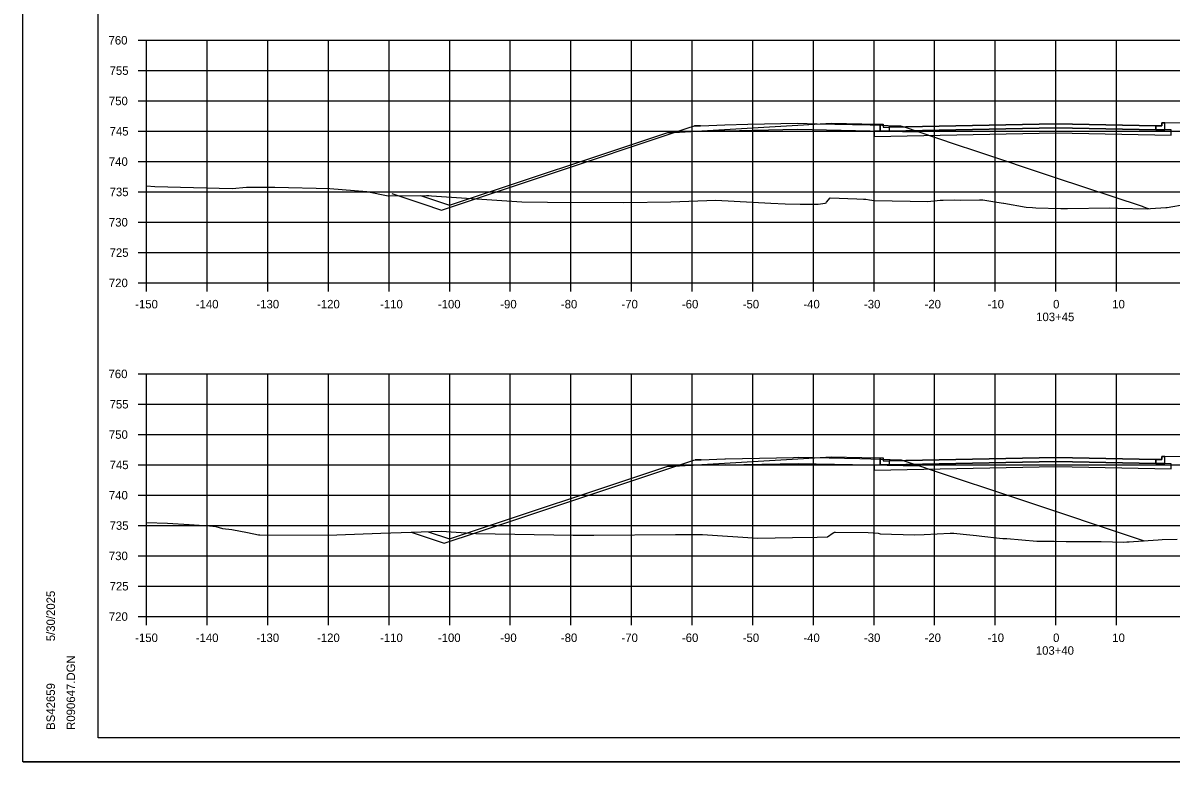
# Model space of a CAD drawing. Extents: x 1202951 to 1376887, y 378065 to 728038.
# Drawn here: x 1374114.6 to 1374304, y 379186.6 to 379308.5 of the extents above; entities that cross this region are included whole.
import ezdxf

# ---------------------------------------------------------------- set-up
doc = ezdxf.new("R2010")
doc.units = 0
for name, color, linetype in [('Default', 7, 'Continuous'), ('R_Alt Surface', 7, 'Continuous'), ('R_Axis', 7, 'Continuous'), ('R_Axis Annot', 7, 'Continuous'), ('R_Exist Surface', 7, 'Continuous'), ('R_Fin Surface', 7, 'Continuous'), ('R_Grid', 7, 'Continuous'), ('R_No Plot', 7, 'Continuous'), ('R_Proposed Road', 7, 'Continuous')]:
    doc.layers.add(name, color=color, linetype=linetype)

msp = doc.modelspace()

# ---------------------------------------------------------------- linework, layer by layer
at = {"layer": 'Default'}
for points in [[(1374255.98, 379291.78), (1374256.47, 379291.78), (1374256.48, 379291.28), (1374257.48, 379291.3), (1374257.48, 379290.64), (1374255.98, 379290.61)], [(1374302.98, 379292), (1374302.49, 379292), (1374302.48, 379291.5), (1374301.48, 379291.52), (1374301.48, 379290.86), (1374302.98, 379290.83)], [(1374255.98, 379236.77), (1374256.47, 379236.77), (1374256.48, 379236.27), (1374257.48, 379236.29), (1374257.48, 379235.62), (1374255.98, 379235.59)], [(1374302.98, 379236.99), (1374302.49, 379236.99), (1374302.48, 379236.49), (1374301.48, 379236.51), (1374301.48, 379235.84), (1374302.98, 379235.81)]]:
    msp.add_lwpolyline(points, close=True, dxfattribs=at)
at = {"layer": 'R_Alt Surface'}
for points in [[(1374284.98, 379291.19), (1374257.48, 379290.64), (1374255.98, 379290.61), (1374254.98, 379290.59), (1374254.98, 379289.75), (1374284.98, 379290.35), (1374303.98, 379289.97), (1374303.98, 379290.81), (1374302.98, 379290.83), (1374301.48, 379290.86)], [(1374257.48, 379291.3), (1374257.48, 379290.64), (1374284.98, 379291.19), (1374301.48, 379290.86), (1374301.48, 379291.52), (1374301.48, 379291.52), (1374284.98, 379291.85), (1374257.48, 379291.3)], [(1374257.48, 379236.29), (1374257.48, 379235.62), (1374284.98, 379236.17), (1374301.48, 379235.84), (1374301.48, 379236.51), (1374301.48, 379236.51), (1374284.98, 379236.84), (1374257.48, 379236.29)], [(1374284.98, 379236.17), (1374257.48, 379235.62), (1374255.98, 379235.59), (1374254.98, 379235.57), (1374254.98, 379234.74), (1374284.98, 379235.34), (1374303.98, 379234.96), (1374303.98, 379235.79), (1374302.98, 379235.81), (1374301.48, 379235.84)]]:
    msp.add_lwpolyline(points, close=True, dxfattribs=at)
for points in [[(1374255.98, 379291.78), (1374255.98, 379290.61), (1374257.48, 379290.64), (1374284.98, 379291.19), (1374301.48, 379290.86), (1374302.98, 379290.83), (1374302.98, 379292)], [(1374230.36, 379290.68), (1374222.36, 379290.52)], [(1374230.36, 379290.68), (1374242.36, 379290.92), (1374254.36, 379290.67)], [(1374254.36, 379290.67), (1374262.36, 379290.51)], [(1374255.98, 379236.77), (1374255.98, 379235.59), (1374257.48, 379235.62), (1374284.98, 379236.17), (1374301.48, 379235.84), (1374302.98, 379235.81), (1374302.98, 379236.99)], [(1374230.46, 379235.61), (1374222.46, 379235.45)], [(1374230.46, 379235.61), (1374242.46, 379235.85), (1374254.47, 379235.6)], [(1374254.47, 379235.6), (1374262.48, 379235.44)]]:
    msp.add_lwpolyline(points, dxfattribs=at)
at = {"layer": 'R_Axis'}
for p, q in [((1374133.58, 379305.6), (1374134.98, 379305.6)), ((1374134.98, 379265.6), (1374134.98, 379305.6)), ((1374133.58, 379300.6), (1374134.98, 379300.6)), ((1374133.58, 379295.6), (1374134.98, 379295.6)), ((1374133.58, 379290.6), (1374134.98, 379290.6)), ((1374133.58, 379285.6), (1374134.98, 379285.6)), ((1374133.58, 379280.6), (1374134.98, 379280.6)), ((1374133.58, 379275.6), (1374134.98, 379275.6)), ((1374133.58, 379270.6), (1374134.98, 379270.6)), ((1374133.58, 379265.6), (1374134.98, 379265.6)), ((1374134.98, 379265.6), (1374434.98, 379265.6)), ((1374134.98, 379264.2), (1374134.98, 379265.6)), ((1374144.98, 379264.2), (1374144.98, 379265.6)), ((1374154.98, 379264.2), (1374154.98, 379265.6)), ((1374164.98, 379264.2), (1374164.98, 379265.6)), ((1374174.98, 379264.2), (1374174.98, 379265.6)), ((1374184.98, 379264.2), (1374184.98, 379265.6)), ((1374194.98, 379264.2), (1374194.98, 379265.6)), ((1374204.98, 379264.2), (1374204.98, 379265.6)), ((1374214.98, 379264.2), (1374214.98, 379265.6)), ((1374224.98, 379264.2), (1374224.98, 379265.6)), ((1374234.98, 379264.2), (1374234.98, 379265.6)), ((1374244.98, 379264.2), (1374244.98, 379265.6)), ((1374254.98, 379264.2), (1374254.98, 379265.6)), ((1374264.98, 379264.2), (1374264.98, 379265.6)), ((1374274.98, 379264.2), (1374274.98, 379265.6)), ((1374284.98, 379264.2), (1374284.98, 379265.6)), ((1374294.98, 379264.2), (1374294.98, 379265.6)), ((1374133.58, 379250.6), (1374134.98, 379250.6)), ((1374134.98, 379210.6), (1374134.98, 379250.6)), ((1374133.58, 379245.6), (1374134.98, 379245.6)), ((1374133.58, 379240.6), (1374134.98, 379240.6)), ((1374133.58, 379235.6), (1374134.98, 379235.6)), ((1374133.58, 379230.6), (1374134.98, 379230.6)), ((1374133.58, 379225.6), (1374134.98, 379225.6)), ((1374133.58, 379220.6), (1374134.98, 379220.6)), ((1374133.58, 379215.6), (1374134.98, 379215.6)), ((1374133.58, 379210.6), (1374134.98, 379210.6)), ((1374134.98, 379210.6), (1374434.98, 379210.6)), ((1374134.98, 379209.2), (1374134.98, 379210.6)), ((1374144.98, 379209.2), (1374144.98, 379210.6)), ((1374154.98, 379209.2), (1374154.98, 379210.6)), ((1374164.98, 379209.2), (1374164.98, 379210.6)), ((1374174.98, 379209.2), (1374174.98, 379210.6)), ((1374184.98, 379209.2), (1374184.98, 379210.6)), ((1374194.98, 379209.2), (1374194.98, 379210.6)), ((1374204.98, 379209.2), (1374204.98, 379210.6)), ((1374214.98, 379209.2), (1374214.98, 379210.6)), ((1374224.98, 379209.2), (1374224.98, 379210.6)), ((1374234.98, 379209.2), (1374234.98, 379210.6)), ((1374244.98, 379209.2), (1374244.98, 379210.6)), ((1374254.98, 379209.2), (1374254.98, 379210.6)), ((1374264.98, 379209.2), (1374264.98, 379210.6)), ((1374274.98, 379209.2), (1374274.98, 379210.6)), ((1374284.98, 379209.2), (1374284.98, 379210.6)), ((1374294.98, 379209.2), (1374294.98, 379210.6))]:
    msp.add_line(p, q, dxfattribs=at)
at = {"layer": 'R_Exist Surface'}
for points in [[(1374134.98, 379281.61), (1374136.31, 379281.52), (1374149.08, 379281.15), (1374151.45, 379281.36), (1374156.13, 379281.36), (1374165.19, 379281.14), (1374171.28, 379280.67), (1374174.8, 379279.96), (1374181.16, 379280.02), (1374181.55, 379280), (1374181.99, 379279.95), (1374196.86, 379278.96), (1374201.1, 379278.89), (1374213.7, 379278.88), (1374221.44, 379278.96), (1374228.91, 379279.23), (1374237.97, 379278.76), (1374240.32, 379278.62), (1374242.8, 379278.57), (1374245.77, 379278.59), (1374246.9, 379278.77), (1374247.07, 379278.79), (1374247.14, 379278.9), (1374247.76, 379279.6), (1374252.12, 379279.46), (1374253.26, 379279.4), (1374253.63, 379279.4), (1374254.21, 379279.28), (1374254.63, 379279.22), (1374255.07, 379279.21), (1374263.84, 379279), (1374265.9, 379279.24), (1374266.41, 379279.25), (1374268.25, 379279.28), (1374269.28, 379279.25), (1374272.38, 379279.27), (1374272.92, 379279.27), (1374275.26, 379278.91), (1374276.34, 379278.74), (1374276.4, 379278.73), (1374280.1, 379278.09), (1374281.14, 379278.01), (1374281.66, 379278), (1374285.79, 379277.85), (1374286.9, 379277.85), (1374293.9, 379277.97), (1374295.2, 379277.94), (1374300.09, 379277.83), (1374300.62, 379277.87), (1374303.14, 379278.06), (1374303.34, 379278.06), (1374309.63, 379279.12)], [(1374134.98, 379226.12), (1374138.41, 379226.02), (1374142.01, 379225.76), (1374145.37, 379225.57), (1374146.39, 379225.45), (1374147.49, 379225.14), (1374149.05, 379224.97), (1374151.6, 379224.46), (1374153.42, 379224.07), (1374153.64, 379224.08), (1374154.84, 379224.03), (1374166.37, 379224.08), (1374173.63, 379224.34), (1374183.65, 379224.66), (1374189.3, 379224.28), (1374205.34, 379224), (1374208.74, 379224), (1374222.22, 379224.14), (1374226.71, 379224.1), (1374235.81, 379223.52), (1374241.54, 379223.63), (1374245.59, 379223.67), (1374247.29, 379223.73), (1374248.24, 379224.41), (1374248.38, 379224.47), (1374248.4, 379224.49), (1374248.61, 379224.49), (1374254.02, 379224.47), (1374255.69, 379224.36), (1374255.99, 379224.22), (1374261.66, 379224.05), (1374263.24, 379224.11), (1374267.56, 379224.35), (1374268.13, 379224.36), (1374269.68, 379224.19), (1374271.87, 379223.98), (1374272.79, 379223.86), (1374275.67, 379223.53), (1374276.22, 379223.45), (1374276.63, 379223.46), (1374276.89, 379223.44), (1374281.86, 379223.04), (1374284.68, 379223.02), (1374286.66, 379222.95), (1374290.13, 379222.95), (1374292.43, 379222.99), (1374296.2, 379222.88), (1374296.67, 379222.91), (1374297.1, 379222.89), (1374297.77, 379222.95), (1374301.86, 379223.24), (1374302.52, 379223.29), (1374304.99, 379223.34)]]:
    msp.add_lwpolyline(points, dxfattribs=at)
at = {"layer": 'R_Fin Surface'}
for points in [[(1374175.43, 379280.35), (1374180.56, 379278.65), (1374183.64, 379277.62), (1374201.61, 379283.61), (1374222.36, 379290.52), (1374224.31, 379291.17), (1374225.36, 379291.52), (1374225.7, 379291.52), (1374226.36, 379291.52), (1374227.72, 379291.57), (1374230.36, 379291.68), (1374234.19, 379291.75), (1374242.36, 379291.92), (1374245.59, 379291.85), (1374254.36, 379291.67), (1374255.24, 379291.64), (1374258.36, 379291.51), (1374259.16, 379291.51), (1374259.36, 379291.51), (1374259.95, 379291.32), (1374262.36, 379290.51), (1374268.56, 379288.44), (1374271.56, 379287.44), (1374284.89, 379283), (1374299.22, 379278.23), (1374299.45, 379278.15), (1374300.2, 379277.89), (1374300.32, 379277.85)], [(1374180.14, 379280.01), (1374184.97, 379278.4), (1374220.97, 379290.4), (1374221.97, 379290.4), (1374247.98, 379291.94), (1374252.98, 379291.84), (1374255.98, 379291.78), (1374256.47, 379291.78), (1374256.48, 379291.28), (1374257.48, 379291.3), (1374284.98, 379291.85), (1374301.48, 379291.52), (1374302.48, 379291.5), (1374302.49, 379292), (1374302.98, 379292), (1374305.98, 379292.06), (1374310.98, 379292.16), (1374312.32, 379291.72), (1374355.87, 379277.2), (1374357.22, 379277.65)], [(1374178.6, 379224.5), (1374180.77, 379223.78), (1374184.08, 379222.68), (1374195.07, 379226.34), (1374222.46, 379235.45), (1374225.28, 379236.39), (1374225.46, 379236.45), (1374226.41, 379236.45), (1374226.46, 379236.45), (1374230.37, 379236.61), (1374230.46, 379236.61), (1374233.26, 379236.67), (1374241.69, 379236.83), (1374242.46, 379236.85), (1374252.62, 379236.64), (1374254.47, 379236.6), (1374257.67, 379236.47), (1374258.47, 379236.44), (1374258.69, 379236.44), (1374259.47, 379236.44), (1374261.76, 379235.68), (1374262.48, 379235.44), (1374264.56, 379234.75), (1374278.82, 379229.98), (1374299.36, 379223.13), (1374299.54, 379223.07)], [(1374181.4, 379224.59), (1374184.96, 379223.4), (1374220.96, 379235.4), (1374221.96, 379235.4), (1374247.98, 379236.93), (1374252.98, 379236.83), (1374255.98, 379236.77), (1374256.47, 379236.77), (1374256.48, 379236.27), (1374257.48, 379236.29), (1374284.98, 379236.84), (1374301.48, 379236.51), (1374302.48, 379236.49), (1374302.49, 379236.99), (1374302.98, 379236.99), (1374305.98, 379237.05)]]:
    msp.add_lwpolyline(points, dxfattribs=at)
at = {"layer": 'R_Grid'}
for p, q in [((1374134.98, 379305.6), (1374434.98, 379305.6)), ((1374134.98, 379265.6), (1374134.98, 379305.6)), ((1374144.98, 379265.6), (1374144.98, 379305.6)), ((1374154.98, 379265.6), (1374154.98, 379305.6)), ((1374164.98, 379265.6), (1374164.98, 379305.6)), ((1374174.98, 379265.6), (1374174.98, 379305.6)), ((1374184.98, 379265.6), (1374184.98, 379305.6)), ((1374194.98, 379265.6), (1374194.98, 379305.6)), ((1374204.98, 379265.6), (1374204.98, 379305.6)), ((1374214.98, 379265.6), (1374214.98, 379305.6)), ((1374224.98, 379265.6), (1374224.98, 379305.6)), ((1374234.98, 379265.6), (1374234.98, 379305.6)), ((1374244.98, 379265.6), (1374244.98, 379305.6)), ((1374254.98, 379265.6), (1374254.98, 379305.6)), ((1374264.98, 379265.6), (1374264.98, 379305.6)), ((1374274.98, 379265.6), (1374274.98, 379305.6)), ((1374284.98, 379265.6), (1374284.98, 379305.6)), ((1374294.98, 379265.6), (1374294.98, 379305.6)), ((1374134.98, 379300.6), (1374434.98, 379300.6)), ((1374134.98, 379295.6), (1374434.98, 379295.6)), ((1374134.98, 379290.6), (1374434.98, 379290.6)), ((1374134.98, 379285.6), (1374434.98, 379285.6)), ((1374134.98, 379280.6), (1374434.98, 379280.6)), ((1374134.98, 379275.6), (1374434.98, 379275.6)), ((1374134.98, 379270.6), (1374434.98, 379270.6)), ((1374134.98, 379265.6), (1374434.98, 379265.6)), ((1374134.98, 379250.6), (1374434.98, 379250.6)), ((1374134.98, 379210.6), (1374134.98, 379250.6)), ((1374144.98, 379210.6), (1374144.98, 379250.6)), ((1374154.98, 379210.6), (1374154.98, 379250.6)), ((1374164.98, 379210.6), (1374164.98, 379250.6)), ((1374174.98, 379210.6), (1374174.98, 379250.6)), ((1374184.98, 379210.6), (1374184.98, 379250.6)), ((1374194.98, 379210.6), (1374194.98, 379250.6)), ((1374204.98, 379210.6), (1374204.98, 379250.6)), ((1374214.98, 379210.6), (1374214.98, 379250.6)), ((1374224.98, 379210.6), (1374224.98, 379250.6)), ((1374234.98, 379210.6), (1374234.98, 379250.6)), ((1374244.98, 379210.6), (1374244.98, 379250.6)), ((1374254.98, 379210.6), (1374254.98, 379250.6)), ((1374264.98, 379210.6), (1374264.98, 379250.6)), ((1374274.98, 379210.6), (1374274.98, 379250.6)), ((1374284.98, 379210.6), (1374284.98, 379250.6)), ((1374294.98, 379210.6), (1374294.98, 379250.6)), ((1374134.98, 379245.6), (1374434.98, 379245.6)), ((1374134.98, 379240.6), (1374434.98, 379240.6)), ((1374134.98, 379235.6), (1374434.98, 379235.6)), ((1374134.98, 379230.6), (1374434.98, 379230.6)), ((1374134.98, 379225.6), (1374434.98, 379225.6)), ((1374134.98, 379220.6), (1374434.98, 379220.6)), ((1374134.98, 379215.6), (1374434.98, 379215.6)), ((1374134.98, 379210.6), (1374434.98, 379210.6))]:
    msp.add_line(p, q, dxfattribs=at)
at = {"layer": 'R_No Plot'}
for p, q in [((1374126.98, 379190.6), (1374126.98, 379396.06)), ((1374126.98, 379190.6), (1374126.98, 379190.6)), ((1374443.16, 379190.6), (1374126.98, 379190.6)), ((1374114.58, 379186.62), (1374447.91, 379186.62))]:
    msp.add_line(p, q, dxfattribs=at)
for points in [[(1374114.57, 379399.95), (1374447.91, 379399.95), (1374447.91, 379186.62), (1374114.57, 379186.62)], [(1374360.9, 379396.06), (1374380.52, 379396.06), (1374380.52, 379386.18), (1374396.63, 379386.18), (1374419.83, 379386.18), (1374419.83, 379361.85), (1374443.16, 379361.85), (1374443.16, 379190.6), (1374126.98, 379190.6), (1374126.98, 379396.06)]]:
    msp.add_lwpolyline(points, close=True, dxfattribs=at)
at = {"layer": 'R_Proposed Road'}
for points in [[(1374226.36, 379291.52), (1374225.36, 379291.52)], [(1374258.36, 379291.51), (1374259.36, 379291.51)], [(1374226.46, 379236.45), (1374225.46, 379236.45)], [(1374258.47, 379236.44), (1374259.47, 379236.44)]]:
    msp.add_lwpolyline(points, dxfattribs=at)

# ---------------------------------------------------------------- texts
at = {"layer": 'R_Axis Annot'}
for s, p in [('760', (1374128.69, 379304.9)), ('755', (1374128.87, 379299.9)), ('750', (1374128.75, 379294.9)), ('745', (1374128.87, 379289.9)), ('740', (1374128.75, 379284.9)), ('735', (1374128.87, 379279.9)), ('730', (1374128.75, 379274.9)), ('725', (1374128.87, 379269.9)), ('720', (1374128.75, 379264.9)), ('-150', (1374133.09, 379261.4)), ('-140', (1374143.09, 379261.4)), ('-130', (1374153.09, 379261.4)), ('-120', (1374163.09, 379261.4)), ('-110', (1374173.49, 379261.4)), ('-100', (1374183.03, 379261.4)), ('-90', (1374193.32, 379261.4)), ('-80', (1374203.32, 379261.4)), ('-70', (1374213.32, 379261.4)), ('-60', (1374223.29, 379261.4)), ('-50', (1374233.32, 379261.4)), ('-40', (1374243.32, 379261.4)), ('-30', (1374253.32, 379261.4)), ('-20', (1374263.32, 379261.4)), ('-10', (1374273.72, 379261.4)), ('0', (1374284.52, 379261.4)), ('10', (1374294.29, 379261.4)), ('103+45', (1374281.73, 379259.3)), ('760', (1374128.69, 379249.9)), ('755', (1374128.87, 379244.9)), ('750', (1374128.75, 379239.9)), ('745', (1374128.87, 379234.9)), ('740', (1374128.75, 379229.9)), ('735', (1374128.87, 379224.9)), ('730', (1374128.75, 379219.9)), ('725', (1374128.87, 379214.9)), ('720', (1374128.75, 379209.9)), ('-150', (1374133.09, 379206.4)), ('-140', (1374143.09, 379206.4)), ('-130', (1374153.09, 379206.4)), ('-120', (1374163.09, 379206.4)), ('-110', (1374173.49, 379206.4)), ('-100', (1374183.03, 379206.4)), ('-90', (1374193.32, 379206.4)), ('-80', (1374203.32, 379206.4)), ('-70', (1374213.32, 379206.4)), ('-60', (1374223.29, 379206.4)), ('-50', (1374233.32, 379206.4)), ('-40', (1374243.32, 379206.4)), ('-30', (1374253.32, 379206.4)), ('-20', (1374263.32, 379206.4)), ('-10', (1374273.72, 379206.4)), ('0', (1374284.52, 379206.4)), ('10', (1374294.29, 379206.4)), ('103+40', (1374281.67, 379204.3))]:
    msp.add_text(s, height=1.4, dxfattribs=at).set_placement(p)
at = {"layer": 'R_No Plot'}
for s, p in [('5/30/2025', (1374119.85, 379206.53)), ('R090647.DGN', (1374123.17, 379191.92)), ('BS42659', (1374119.85, 379191.92))]:
    msp.add_text(s, height=1.4, rotation=90, dxfattribs=at).set_placement(p)

doc.saveas('drawing.dxf')
